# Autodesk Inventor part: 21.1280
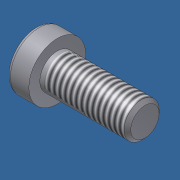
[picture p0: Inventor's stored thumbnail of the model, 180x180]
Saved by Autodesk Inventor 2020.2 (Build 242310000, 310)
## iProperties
Created: 2006-02
Part Number: 21.1280
Material: Steel, Mild
Description: M8X22 SHCS
Document SubType Name: Modeling
Standard: DIN 7984
Designer: Andy Moles
Standards Organization: DIN
Language: en-US
Size Designation: M8 x 20
Categories: <MemberInstance><Categories><Category DisplayName="Fasteners" InternalName="e4da775c-781d-43d5-af7c-5136215cf5a6" Mnemonic="FSTN"><Category DisplayName="Bolts"
Density: 7.85 g/cm^3
Mass: 13.0366 g
Surface Area: 10.6794 cm^2
Volume: 1.66071 cm^3
Vendor: S
Appearance: Zinc
Author: Andy Moles
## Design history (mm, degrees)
sketch "Sketch1"
  geometry: L1 (0.467, 0)-(22, 0); L2 (22, 0)-(22, 4); L3 (22, 4)-(1, 4); L4 (1, 4)-(0.233, 4); L5 (0.233, 4)-(0, 4); L6 (0, 4)-(0, 6.5); L7 (0, 6.5)-(-5, 6.5); L8 (-5, 6.5)-(-5, 2.887); L9 (-5, 2.887)-(-1.2, 2.887); L10 (-1.2, 2.887)-(0.467, 0); L11 (-7.5, 0)-(27.5, 0) reference; L12 (0, -0.65)-(0, 8.45) reference; L13 (1, 4)-(0, 4)
  constraints: 22 end point, 6 parallel, 2 collinear, 2 perpendicular, 1 horizontal, 1 point on line
  dimensions: "d1" = 21 distance from line of L3.end L2 (= GEL); "d2" = 0.76691 distance of L4.end L3.end (computed from GAL); "d3" = 5 distance between parallel lines of L8 L6 (= KOH); "d4" = 3.8 distance of L8.end L9.end (= INTI); "d5" = 60 deg angle of L10 L1; "d6" = 8 diameter of L3 L1 (= GD); "d7" = 8 diameter of L5 L1 (= BDM); "d8" = 5.7735 diameter of L9 L1 (= 1.1547 x SW); "d9" = 13 diameter of L7 L1 (= KOD); "d26" = 22 distance between parallel lines of L12 L2 (= NLG)
revolve "Body" sketch "Sketch1" stored, may be unused: angle "d10" = 90 deg
sketch "Sketch2"
  geometry: L1 (0, -7.8)-(0, 10.4) reference; L2 (-7.8, 0)-(10.4, 0) reference; L3 (2.887, 0)-(1.443, -2.5); L4 (1.443, -2.5)-(-1.443, -2.5); L5 (-1.443, -2.5)-(-2.887, 0); L6 (-2.887, 0)-(-1.443, 2.5); L7 (-1.443, 2.5)-(1.443, 2.5); L8 (1.443, 2.5)-(2.887, 0); 2 further points
  constraints: 12 end point, 1 coincident, 1 horizontal alignment, 1 point on line, 12 other
extrude "Slot" join sketch "Sketch2" stored distance "d11" = 10; taper "d12" = 0 deg
workplane "Work Plane1"
body "Solid1"
fillet "Fillet1" dims "d17" = 0.8 (= RR)
feature "Thread" dims "d13" = 22, "d14" = 0
chamfer "Chamfer1" distance "d15" = 0.76681 (= -0.5 x SPD + 0.5 x GD); stored, may be unused: second distance "d16" = 0.76681 (= GUL), angle "d27" = 45 deg
other parameters: "GD" = 8 (= NND) [user parameter; used in 2 equation terms], "NLG" = 22 [user parameter; used in 1 equation term], "GEL" = 21 [user parameter; used in 1 equation term], "KOD" = 13 [user parameter; used in 1 equation term], "KOH" = 5 [user parameter; used in 1 equation term], "INTI" = 3.8 [user parameter; used in 1 equation term], "GAL" = 0.76681 (= 0.61345 x PTC) [user parameter; used in 1 equation term], "GUL" = 0.76681 (= 0.61345 x PTC) [user parameter; used in 1 equation term], "BDM" = 8 (= NND) [user parameter; used in 1 equation term], "SW" = 5 [user parameter; used in 2 equation terms], "RR" = 0.8 [user parameter; used in 1 equation term], "SPD" = 6.46637 (= NND - 1.2269 x PTC) [user parameter; used in 1 equation term], "d19" = 0, "d28" = 0, "d29" = 0, "TOA" = 30 deg [user parameter], "GD1" = 6.46637 (= THREADDIA - 1.2269 x PTC) [user parameter], "THREADDIA" = 8 [user parameter; used in 1 equation term], "FAWI" = 45 deg [user parameter], "ANG" = 120 deg [user parameter], "TPU" = 8 (computed from PTC) [user parameter], "PTC" = 1.25 [user parameter; used in 5 equation terms], "NND" = 8 [user parameter; used in 3 equation terms], "E0" = 5.775 (= 1.155 x SW) [user parameter]
